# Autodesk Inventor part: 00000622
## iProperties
Created: 2011-05
Part Number: 00000622
Document SubType Name: Modeling
Designer: Administrator
Density: 7.85 g/cm^3
Material: Steel
Mass: 9.53447 g
Surface Area: 8.66806 cm^2
Volume: 1.21458 cm^3
Author: Administrator
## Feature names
1. Base1
